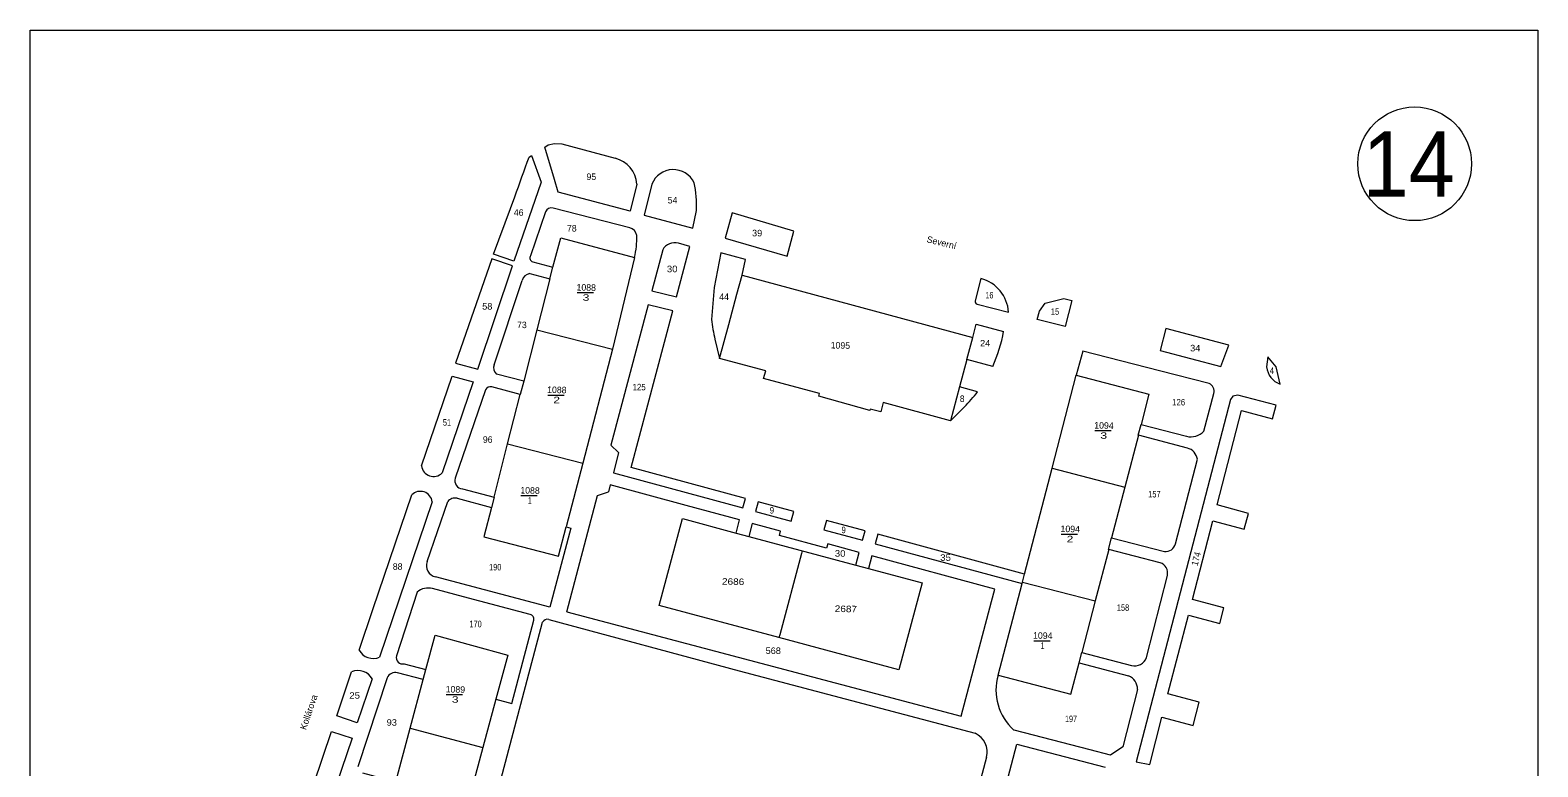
# Model space of a CAD drawing. Extents: x -843408 to -843177, y -1002968 to -1002716.
# Drawn here: x -843408.2 to -843176.9, y -1002829 to -1002715.9 of the extents above; entities that cross this region are included whole.
import ezdxf
from ezdxf.enums import TextEntityAlignment as Align

# ---------------------------------------------------------------- set-up
doc = ezdxf.new("R2010")
doc.units = 0
doc.header["$LTSCALE"] = 0.4
doc.layers.add('20', color=7, linetype='Continuous')
for name, color, linetype, lineweight in [('35', 7, 'Continuous', 13), ('38', 7, 'Continuous', 13), ('43', 7, 'Continuous', 13), ('44', 7, 'Continuous', 13)]:
    doc.layers.add(name, color=color, linetype=linetype, lineweight=lineweight)

msp = doc.modelspace()

# ---------------------------------------------------------------- linework, layer by layer
at = {"layer": '35'}
for p, q in [((-843324.255, -1002756.21), (-843321.755, -1002756.21)), ((-843328.762, -1002771.93), (-843326.262, -1002771.93)), ((-843244.842, -1002777.389), (-843242.342, -1002777.389)), ((-843332.877, -1002787.355), (-843330.377, -1002787.355)), ((-843250.016, -1002793.266), (-843247.516, -1002793.266)), ((-843254.227, -1002809.625), (-843251.727, -1002809.625)), ((-843344.325, -1002817.878), (-843341.825, -1002817.878))]:
    msp.add_line(p, q, dxfattribs=at)
at = {"layer": '38'}
for p, q in [((-843328.445, -1002754.094), (-843327.987, -1002752.304)), ((-843298.97, -1002753.52), (-843263.55, -1002763.08)), ((-843330.45, -1002761.94), (-843318.83, -1002764.91)), ((-843264.465, -1002766.474), (-843265.598, -1002770.672)), ((-843332.46, -1002769.806), (-843332.98, -1002771.84)), ((-843238.186, -1002778.095), (-843237.757, -1002776.445)), ((-843334.92, -1002779.43), (-843323.4, -1002782.38)), ((-843251.39, -1002783.14), (-843240.25, -1002786.04)), ((-843337.002, -1002787.591), (-843337.402, -1002789.16)), ((-843299.871, -1002793.096), (-843297.939, -1002793.614)), ((-843242.74, -1002795.606), (-843242.279, -1002793.834)), ((-843281.506, -1002798.021), (-843279.574, -1002798.539)), ((-843259.68, -1002814.9), (-843256.017, -1002800.838)), ((-843255.96, -1002800.62), (-843244.8, -1002803.52)), ((-843247.271, -1002813.03), (-843246.856, -1002811.433)), ((-843347.869, -1002815.581), (-843347.448, -1002814.018)), ((-843349.87, -1002823.01), (-843338.72, -1002826.01))]:
    msp.add_line(p, q, dxfattribs=at)
for points in [[(-843315.466, -1002750.808), (-843318.83, -1002764.91), (-843323.4, -1002782.38), (-843325.961, -1002792.157)], [(-843267, -1002775.87), (-843277.3, -1002773.09), (-843277.69, -1002774.52), (-843279.3, -1002774.08), (-843279.36, -1002774.31), (-843287.19, -1002772.09), (-843287.08, -1002771.69), (-843295.65, -1002769.38), (-843295.33, -1002768.22), (-843302.42, -1002766.31)], [(-843255.638, -1002799.387), (-843251.39, -1002783.14), (-843247.69, -1002768.9)], [(-843271.36, -1002800.74), (-843274.94, -1002814.07), (-843293.3, -1002809.14), (-843311.66, -1002804.21), (-843308.09, -1002790.89)], [(-843289.72, -1002795.82), (-843289.83, -1002796.25), (-843293.18, -1002808.71), (-843293.3, -1002809.14)], [(-843336.717, -1002818.592), (-843338.72, -1002826.01), (-843343.42, -1002843.52), (-843345.424, -1002850.965)]]:
    msp.add_lwpolyline(points, dxfattribs=at)
at = {"layer": '43'}
for p, q in [((-843329.11, -1002743.84), (-843331.4, -1002750.55)), ((-843316.2, -1002746.27), (-843327.93, -1002743.24)), ((-843326.74, -1002747.82), (-843315.466, -1002750.808)), ((-843337.01, -1002767.28), (-843332.71, -1002754.33)), ((-843331.533, -1002753.276), (-843328.445, -1002754.094)), ((-843262.321, -1002754.043), (-843263.184, -1002757.456)), ((-843262.884, -1002758.003), (-843258.097, -1002759.213)), ((-843218.3, -1002766.04), (-843218.506, -1002767.601)), ((-843340.229, -1002769.891), (-843344.976, -1002783.88)), ((-843338.34, -1002771.15), (-843342.95, -1002784.69)), ((-843332.98, -1002771.84), (-843337.33, -1002770.67)), ((-843228.11, -1002777.46), (-843226.596, -1002771.678)), ((-843267, -1002775.87), (-843264.849, -1002773.733)), ((-843232.48, -1002794.74), (-843229.11, -1002781.77)), ((-843325.851, -1002805.175), (-843321.125, -1002787.339)), ((-843321.125, -1002787.339), (-843319.434, -1002786.762)), ((-843319.17, -1002785.719), (-843319.434, -1002786.762)), ((-843346.478, -1002788.306), (-843354.56, -1002812.12)), ((-843347.28, -1002797.48), (-843344.12, -1002788.28)), ((-843236.93, -1002812.21), (-843233.73, -1002799.59)), ((-843348.791, -1002802.146), (-843351.96, -1002811.93)), ((-843334.293, -1002819.246), (-843330.909, -1002806.44)), ((-843247.271, -1002813.03), (-843239.667, -1002815.004)), ((-843361.138, -1002821.158), (-843358.85, -1002814.404)), ((-843353.41, -1002815.31), (-843357.88, -1002828.97)), ((-843347.869, -1002815.581), (-843351.81, -1002814.54)), ((-843358.786, -1002824.594), (-843365.612, -1002844.742))]:
    msp.add_line(p, q, dxfattribs=at)
for points in [[(-843327.75, -1002738.83), (-843329.234, -1002733.906), (-843328.68, -1002733.56), (-843327.72, -1002733.31), (-843326.63, -1002733.36), (-843318.423, -1002735.593)], [(-843331.63, -1002735.41), (-843331.276, -1002735.187), (-843329.793, -1002739.282)], [(-843329.793, -1002739.282), (-843333.954, -1002751.402), (-843337.108, -1002750.332), (-843334.49, -1002743.29), (-843333.823, -1002741.495)], [(-843315.088, -1002739.558), (-843316.112, -1002743.736), (-843327.19, -1002740.8), (-843327.75, -1002738.83)], [(-843312.797, -1002739.558), (-843313.961, -1002744.306), (-843306.518, -1002746.343), (-843305.964, -1002743.612)], [(-843331.06, -1002751.49), (-843327.987, -1002752.304), (-843326.74, -1002747.82)], [(-843311.14, -1002749.66), (-843312.801, -1002755.927), (-843309.006, -1002756.832)], [(-843309.006, -1002756.832), (-843306.96, -1002749.11), (-843308.733, -1002748.641)], [(-843299.763, -1002756.461), (-843298.97, -1002753.52), (-843298.412, -1002751.124), (-843302.2, -1002750.12), (-843303.249, -1002755.407), (-843303.631, -1002760.333)], [(-843328.445, -1002754.094), (-843330.45, -1002761.94), (-843332.46, -1002769.806), (-843336.61, -1002768.7)], [(-843303.129, -1002763.362), (-843302.42, -1002766.31), (-843301.017, -1002761.11), (-843299.763, -1002756.461)], [(-843260.515, -1002767.539), (-843264.465, -1002766.474), (-843263.55, -1002763.08), (-843263.06, -1002761.05), (-843258.85, -1002762.16)], [(-843246.705, -1002765.206), (-843247.69, -1002768.9), (-843236.55, -1002771.8), (-843237.757, -1002776.445), (-843230.79, -1002778.25)], [(-843227.33, -1002770.14), (-843234.951, -1002768.199), (-843246.705, -1002765.206)], [(-843216.44, -1002770.257), (-843217.04, -1002767.58), (-843218.3, -1002766.04)], [(-843348.13, -1002782.81), (-843343.451, -1002769.024), (-843340.229, -1002769.891)], [(-843262.832, -1002771.418), (-843265.598, -1002770.672), (-843267, -1002775.87)], [(-843341.85, -1002786.31), (-843337.002, -1002787.591), (-843334.92, -1002779.43), (-843332.98, -1002771.84)], [(-843230.653, -1002780.054), (-843238.144, -1002778.103), (-843240.25, -1002786.04)], [(-843357.714, -1002811.05), (-843355.543, -1002804.653), (-843349.632, -1002787.236)], [(-843342.639, -1002787.772), (-843337.402, -1002789.16), (-843338.56, -1002793.7), (-843327.13, -1002796.62), (-843325.961, -1002792.157), (-843325.252, -1002792.343)], [(-843260.187, -1002801.691), (-843279.05, -1002796.583), (-843279.574, -1002798.539), (-843271.36, -1002800.74), (-843274.94, -1002814.07), (-843293.3, -1002809.14), (-843311.66, -1002804.21), (-843308.09, -1002790.89), (-843299.871, -1002793.096), (-843299.333, -1002791.091), (-843307.548, -1002788.866), (-843319.17, -1002785.719)], [(-843240.25, -1002786.04), (-843242.279, -1002793.834), (-843234.19, -1002795.94)], [(-843325.252, -1002792.343), (-843328.469, -1002804.482), (-843345.99, -1002799.84)], [(-843234.825, -1002797.671), (-843242.706, -1002795.619), (-843244.8, -1002803.52)], [(-843331.466, -1002805.592), (-843340.91, -1002803.09), (-843346.461, -1002801.619)], [(-843325.851, -1002805.175), (-843265.33, -1002821.21), (-843260.693, -1002803.601), (-843260.187, -1002801.691)], [(-843244.8, -1002803.52), (-843246.856, -1002811.433), (-843239.22, -1002813.42)], [(-843328.62, -1002806.347), (-843299.41, -1002814.22), (-843263.22, -1002823.82)], [(-843345.387, -1002866.68), (-843340.42, -1002847.88), (-843340.395, -1002847.784), (-843339.341, -1002847.711), (-843336.998, -1002838.843), (-843337.84, -1002838.116), (-843334.981, -1002827.292), (-843329.565, -1002806.795)], [(-843350.77, -1002813.14), (-843347.448, -1002814.018), (-843346.04, -1002808.79), (-843334.9, -1002811.86), (-843336.717, -1002818.592), (-843334.293, -1002819.246)], [(-843259.68, -1002814.9), (-843248.51, -1002817.8), (-843247.271, -1002813.03)], [(-843355.696, -1002815.474), (-843357.984, -1002822.227), (-843361.138, -1002821.158)], [(-843357.162, -1002829.902), (-843352.085, -1002831.243), (-843349.87, -1002823.01), (-843347.869, -1002815.581)], [(-843238.3, -1002817.09), (-843240.55, -1002825.9), (-843242.46, -1002827.17), (-843245.56, -1002826.363), (-843257.25, -1002823.318)], [(-843368.765, -1002843.672), (-843361.94, -1002823.526), (-843358.786, -1002824.594)], [(-843258.72, -1002832.69), (-843256.83, -1002825.491), (-843243.25, -1002829.04)], [(-843261.48, -1002827.5), (-843265.045, -1002840.992), (-843266.14, -1002841.225)]]:
    msp.add_lwpolyline(points, dxfattribs=at)
for points in [[(-843301.569, -1002747.831), (-843292.063, -1002750.629), (-843291.007, -1002746.798), (-843300.506, -1002743.977)], [(-843339.481, -1002767.935), (-843334.191, -1002752.1), (-843337.345, -1002751.03), (-843342.898, -1002767.025)], [(-843248.366, -1002757.445), (-843249.403, -1002761.41), (-843253.676, -1002760.33), (-843253.33, -1002759.08), (-843252.46, -1002757.83), (-843249.59, -1002757.13)], [(-843298.441, -1002787.797), (-843315.955, -1002783.054), (-843309.576, -1002758.983), (-843313.371, -1002758.078), (-843319.079, -1002779.618), (-843317.909, -1002780.743), (-843318.7, -1002783.865), (-843298.833, -1002789.244)], [(-843234.848, -1002765.089), (-843225.51, -1002767.53), (-843224.3, -1002764.27), (-843233.973, -1002761.741)], [(-843217.02, -1002773.48), (-843222.93, -1002771.93), (-843223.68, -1002772.12), (-843224.04, -1002772.61), (-843238.49, -1002828.19), (-843236.41, -1002828.59), (-843234.56, -1002821.36), (-843229.78, -1002822.61), (-843228.84, -1002819.06), (-843233.63, -1002817.79), (-843230.5, -1002805.69), (-843225.68, -1002806.99), (-843225.08, -1002804.58), (-843229.88, -1002803.28), (-843226.73, -1002791.23), (-843221.95, -1002792.48), (-843221.27, -1002790.09), (-843226.11, -1002788.78), (-843222.36, -1002774.31), (-843217.58, -1002775.57)], [(-843296.902, -1002789.767), (-843291.416, -1002791.253), (-843291.024, -1002789.805), (-843296.51, -1002788.319)], [(-843293.237, -1002793.467), (-843293.054, -1002792.791), (-843297.402, -1002791.614), (-843297.939, -1002793.614), (-843281.506, -1002798.021), (-843280.98, -1002796.06), (-843285.807, -1002794.754), (-843285.99, -1002795.429)], [(-843286.399, -1002792.611), (-843280.48, -1002794.214), (-843280.088, -1002792.766), (-843286.007, -1002791.163)], [(-843278.55, -1002794.737), (-843256.017, -1002800.838), (-843255.638, -1002799.387), (-843278.158, -1002793.289)]]:
    msp.add_lwpolyline(points, close=True, dxfattribs=at)
for centre, radius, start, end in [((-844523.6875, -1002309.3006), 1265.9266, 340.03749, 340.33021), ((-843319.4519, -1002739.844), 4.3733, 3.7489, 76.39797), ((-843309.5161, -1002740.8574), 3.5295, 25.10424, 158.38955), ((-843320.2015, -1002742.6618), 14.2688, 356.17963, 13.37938), ((-843328.2115, -1002744.1466), 0.9493, 72.74819, 161.15617), ((-843316.5668, -1002747.6899), 1.4666, 9.41647, 75.51641), ((-843327.0132, -1002747.9206), 11.9025, 345.9633, 2.26616), ((-843330.9042, -1002750.9022), 0.6081, 144.61227, 255.15807), ((-843309.2787, -1002750.7034), 2.1338, 75.16906, 150.72686), ((-843331.2004, -1002754.8313), 1.5907, 102.07903, 161.63144), ((-843263.764, -1002759.5316), 5.6755, 3.22022, 75.27318), ((-843262.74, -1002757.5684), 0.4579, 165.81644, 251.60334), ((-843282.3898, -1002758.3708), 21.3318, 185.27809, 193.53171), ((-843279.8825, -1002758.5992), 21.3318, 335.22188, 350.39095), ((-843335.9158, -1002767.7381), 1.1862, 157.28147, 234.18254), ((-843215.2921, -1002767.2323), 3.2348, 186.55164, 249.21441), ((-843337.5537, -1002771.5019), 0.8615, 74.94998, 155.8886), ((-843279.8825, -1002758.5992), 21.3318, 314.80958, 323.0632), ((-843227.9209, -1002771.3661), 1.3611, 346.74528, 64.26762), ((-843230.1087, -1002775.6206), 2.7163, 255.47308, 317.37544), ((-843231.2, -1002782.0973), 2.1155, 8.90014, 75.00568), ((-843346.287, -1002782.5609), 1.8597, 187.69645, 314.81231), ((-843341.7892, -1002785.0852), 1.2263, 161.19769, 267.15628), ((-843348.3241, -1002788.5634), 1.8636, 7.93682, 134.57194), ((-843342.9996, -1002789.1334), 1.4084, 75.15386, 142.70249), ((-843234.0406, -1002794.3345), 1.6124, 264.68397, 345.43489), ((-843345.5582, -1002798.0714), 1.8205, 161.04352, 256.27941), ((-843235.273, -1002799.1987), 1.5918, 345.77163, 73.65225), ((-843347.1219, -1002804.1114), 2.5785, 75.15806, 130.3483), ((-843331.5678, -1002806.2659), 0.681, 345.20083, 81.44529), ((-843328.7931, -1002807.203), 0.8735, 78.55019, 152.15101), ((-843355.5632, -1002809.8944), 2.4412, 208.2454, 294.26336), ((-843351.0496, -1002812.2248), 0.9569, 162.05414, 286.99096), ((-843238.7366, -1002811.5628), 1.919, 255.41075, 340.29179), ((-843357.8469, -1002816.6297), 2.4412, 28.2454, 114.26336), ((-843352.1592, -1002815.8617), 1.3671, 75.20083, 156.19754), ((-843251.8953, -1002817.2128), 8.121, 163.45388, 228.74466), ((-843240.4882, -1002817.0329), 2.189, 358.50475, 67.97481), ((-843264.5346, -1002826.693), 3.1595, 345.20057, 65.41144)]:
    msp.add_arc(centre, radius, start, end, dxfattribs=at)
at = {"layer": '44'}
msp.add_lwpolyline([(-843176.897, -1002715.941), (-843176.897, -1002968.008), (-843408.163, -1002968.008), (-843408.163, -1002715.941)], close=True, dxfattribs=at)
msp.add_circle((-843195.7965, -1002736.4476), 8.721, dxfattribs=at)

# ---------------------------------------------------------------- texts
at = {"layer": '20'}
for s, rotation, p in [('Severní', 346.137, (-843270.708, -1002748.473)), ('Kollárova', 71.148, (-843365.856, -1002823.378))]:
    msp.add_text(s, height=1, rotation=rotation, dxfattribs=at).set_placement(p)
at = {"layer": '35'}
for s, p in [('1088', (-843322.8745, -1002755.9127)), ('1095', (-843283.8935, -1002764.8077)), ('1088', (-843327.382, -1002771.6327)), ('1094', (-843243.46, -1002777.0911)), ('1088', (-843331.4955, -1002787.0577)), ('1094', (-843248.634, -1002792.9691)), ('1094', (-843252.8465, -1002809.3281)), ('1089', (-843342.945, -1002817.5814))]:
    msp.add_text(s, height=1, rotation=358.734, dxfattribs=at).set_placement(p, align=Align.CENTER)
for s, width, p in [('3', 1.4, (-843322.9095, -1002757.4625)), ('2', 1.35, (-843327.415, -1002773.1823)), ('3', 1.4, (-843243.4955, -1002778.6415)), ('1', 0.7, (-843331.5305, -1002788.6068)), ('2', 1.35, (-843248.669, -1002794.5183)), ('2686', 1.15, (-843300.345, -1002801.0466)), ('2687', 1.15, (-843283.048, -1002805.235)), ('1', 0.7, (-843252.8805, -1002810.8768)), ('3', 1.4, (-843342.9785, -1002819.1305))]:
    msp.add_text(s, height=1, rotation=358.734, dxfattribs=dict(at, width=width)).set_placement(p, align=Align.CENTER)
at = {"layer": '43'}
for s, p in [('95', (-843322.827, -1002738.929)), ('54', (-843310.371, -1002742.531)), ('46', (-843333.973, -1002744.421)), ('78', (-843325.82, -1002746.838)), ('44', (-843302.463, -1002757.345)), ('73', (-843333.477, -1002761.659)), ('96', (-843338.723, -1002779.252)), ('88', (-843352.538, -1002798.74))]:
    msp.add_text(s, height=1, dxfattribs=at).set_placement(p)
for s, width, p in [('39', 1.05, (-843297.436, -1002747.577)), ('30', 1.1, (-843310.498, -1002753.082)), ('58', 1.05, (-843338.823, -1002758.817)), ('16', 0.7, (-843261.646, -1002757.104)), ('15', 0.75, (-843251.596, -1002759.615)), ('24', 1.05, (-843262.457, -1002764.474)), ('34', 1.05, (-843230.229, -1002765.225)), ('4', 0.9, (-843218.023, -1002768.685)), ('125', 0.9, (-843315.756, -1002771.208)), ('8', 0.95, (-843265.548, -1002772.993)), ('126', 0.9, (-843233.001, -1002773.522)), ('51', 0.75, (-843344.865, -1002776.625)), ('157', 0.85, (-843236.66, -1002787.635)), ('9', 0.9, (-843294.722, -1002790.107)), ('9', 0.9, (-843283.715, -1002793.121)), ('30', 1.1, (-843284.735, -1002796.723)), ('35', 1.1, (-843268.567, -1002797.362)), ('190', 0.85, (-843337.777, -1002798.834)), ('158', 0.85, (-843241.472, -1002805.031)), ('170', 0.85, (-843340.795, -1002807.553)), ('568', 1.05, (-843295.353, -1002811.65)), ('25', 1.1, (-843359.209, -1002818.516)), ('93', 1.05, (-843353.475, -1002822.654)), ('197', 0.8, (-843249.422, -1002822.107))]:
    msp.add_text(s, height=1, dxfattribs=dict(at, width=width)).set_placement(p)
at = {"layer": '43', "width": 0.95}
msp.add_text('174', height=0.999, rotation=75.427, dxfattribs=at).set_placement((-843229.098, -1002798.204))
at = {"layer": '44', "width": 0.95}
msp.add_text('14', height=10, dxfattribs=at).set_placement((-843203.783, -1002741.488))

doc.saveas('drawing.dxf')
